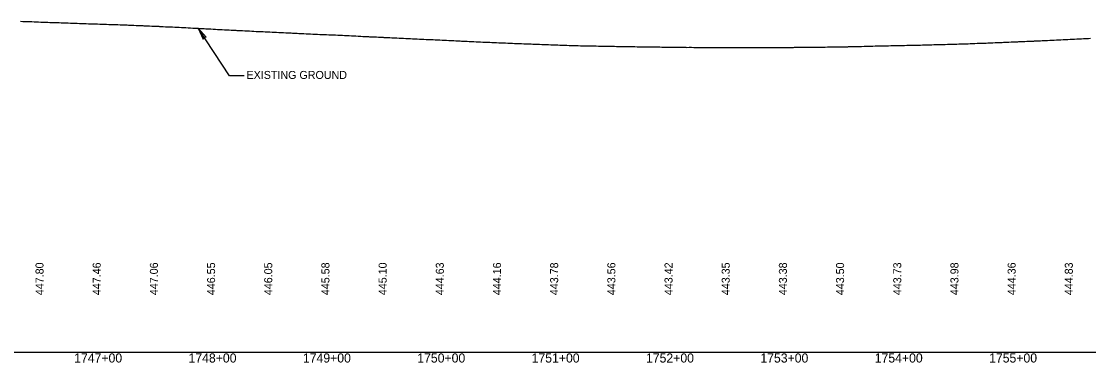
# Model space of a CAD drawing. Extents: x 2017200 to 2047700, y 854850 to 893350.
# Drawn here: x 2029630 to 2030563, y 859091 to 859390 of the extents above; entities that cross this region are included whole.
import ezdxf

# ---------------------------------------------------------------- set-up
doc = ezdxf.new("R2010")
doc.units = 0
for name, color, linetype in [('RD_DDB_Profile_EX', 7, 'Continuous'), ('RD_DDB_Profile_Lbl', 7, 'Continuous'), ('RD_DDB_StaTX', 7, 'Continuous'), ('RD_DDB_StripGrade', 7, 'Continuous'), ('RD_GPK_Profile_Cell', 7, 'Continuous')]:
    doc.layers.add(name, color=color, linetype=linetype)

msp = doc.modelspace()

# ---------------------------------------------------------------- linework, layer by layer
at = {"layer": 'RD_DDB_Profile_EX'}
msp.add_lwpolyline([(2029628.81, 859389.7), (2029630.78, 859389.63), (2029632.79, 859389.56), (2029634.76, 859389.54), (2029635.28, 859389.53), (2029636.74, 859389.5), (2029638.72, 859389.41), (2029640.76, 859389.34), (2029642.05, 859389.3), (2029642.76, 859389.28), (2029644.74, 859389.19), (2029646.72, 859389.09), (2029648.82, 859389.03), (2029650.67, 859389), (2029652.68, 859388.89), (2029654.65, 859388.81), (2029655.59, 859388.79), (2029656.63, 859388.75), (2029658.61, 859388.7), (2029660.58, 859388.6), (2029662.58, 859388.54), (2029664.56, 859388.48), (2029666.54, 859388.41), (2029668.52, 859388.31), (2029669.13, 859388.3), (2029670.5, 859388.26), (2029672.51, 859388.2), (2029674.48, 859388.13), (2029675.9, 859388.07), (2029676.46, 859388.05), (2029678.43, 859387.98), (2029680.4, 859387.9), (2029682.67, 859387.8), (2029684.38, 859387.76), (2029686.36, 859387.71), (2029688.33, 859387.61), (2029689.44, 859387.58), (2029690.31, 859387.55), (2029692.31, 859387.51), (2029694.28, 859387.44), (2029696.26, 859387.37), (2029698.24, 859387.32), (2029700.22, 859387.28), (2029702.22, 859387.21), (2029702.98, 859387.18), (2029704.19, 859387.13), (2029706.17, 859387.06), (2029708.14, 859387.04), (2029709.75, 859386.96), (2029710.11, 859386.95), (2029712.11, 859386.87), (2029714.08, 859386.81), (2029716.06, 859386.75), (2029716.52, 859386.73), (2029718.03, 859386.66), (2029720, 859386.57), (2029722, 859386.51), (2029723.29, 859386.44), (2029723.98, 859386.41), (2029725.96, 859386.3), (2029727.93, 859386.24), (2029730.06, 859386.16), (2029731.91, 859386.06), (2029733.89, 859385.99), (2029735.86, 859385.94), (2029736.83, 859385.89), (2029737.84, 859385.83), (2029739.81, 859385.72), (2029741.81, 859385.66), (2029743.79, 859385.58), (2029745.77, 859385.48), (2029747.75, 859385.39), (2029749.73, 859385.34), (2029750.37, 859385.3), (2029751.73, 859385.22), (2029753.71, 859385.12), (2029755.69, 859384.99), (2029757.14, 859384.97), (2029757.67, 859384.96), (2029759.65, 859384.86), (2029761.66, 859384.74), (2029763.91, 859384.65), (2029765.61, 859384.55), (2029767.59, 859384.45), (2029769.56, 859384.34), (2029770.68, 859384.3), (2029771.56, 859384.26), (2029773.54, 859384.15), (2029775.52, 859384.05), (2029777.49, 859383.95), (2029779.47, 859383.85), (2029781.47, 859383.74), (2029783.45, 859383.64), (2029784.22, 859383.6), (2029785.42, 859383.54), (2029787.4, 859383.43), (2029789.37, 859383.32), (2029790.99, 859383.24), (2029791.37, 859383.22), (2029793.35, 859383.1), (2029795.32, 859382.99), (2029797.3, 859382.87), (2029797.76, 859382.84), (2029799.27, 859382.77), (2029801.27, 859382.68), (2029803.26, 859382.58), (2029804.53, 859382.51), (2029805.24, 859382.47), (2029807.22, 859382.36), (2029809.2, 859382.26), (2029811.3, 859382.16), (2029813.18, 859382.05), (2029815.16, 859381.97), (2029817.13, 859381.87), (2029818.07, 859381.81), (2029819.11, 859381.75), (2029821.11, 859381.65), (2029823.09, 859381.56), (2029825.06, 859381.46), (2029827.04, 859381.33), (2029829.01, 859381.25), (2029831.01, 859381.14), (2029831.61, 859381.11), (2029832.99, 859381.03), (2029834.96, 859380.93), (2029836.94, 859380.87), (2029838.38, 859380.79), (2029838.91, 859380.75), (2029840.92, 859380.65), (2029842.89, 859380.56), (2029845.15, 859380.48), (2029845.53, 859380.46), (2029846.84, 859380.39), (2029848.82, 859380.31), (2029850.82, 859380.22), (2029851.92, 859380.17), (2029852.8, 859380.12), (2029854.78, 859380.03), (2029856.75, 859379.94), (2029858.73, 859379.84), (2029860.73, 859379.76), (2029862.71, 859379.69), (2029864.69, 859379.57), (2029865.46, 859379.53), (2029866.67, 859379.46), (2029868.64, 859379.39), (2029870.65, 859379.26), (2029872.23, 859379.18), (2029872.62, 859379.15), (2029874.6, 859379.07), (2029876.58, 859378.97), (2029878.55, 859378.84), (2029879, 859378.83), (2029880.56, 859378.77), (2029882.53, 859378.7), (2029884.51, 859378.57), (2029885.77, 859378.51), (2029886.49, 859378.48), (2029888.46, 859378.4), (2029890.47, 859378.3), (2029892.54, 859378.21), (2029894.42, 859378.14), (2029896.4, 859378.06), (2029898.37, 859377.97), (2029899.31, 859377.93), (2029900.38, 859377.88), (2029902.36, 859377.8), (2029904.33, 859377.75), (2029906.31, 859377.62), (2029908.29, 859377.54), (2029910.29, 859377.46), (2029912.27, 859377.39), (2029912.85, 859377.35), (2029914.24, 859377.27), (2029916.22, 859377.18), (2029918.2, 859377.11), (2029919.62, 859377.01), (2029920.2, 859376.98), (2029922.18, 859376.89), (2029924.16, 859376.8), (2029926.39, 859376.64), (2029928.11, 859376.55), (2029930.11, 859376.5), (2029932.09, 859376.41), (2029933.16, 859376.33), (2029934.07, 859376.27), (2029936.04, 859376.17), (2029938.02, 859376.13), (2029940.02, 859376.01), (2029942, 859375.89), (2029943.98, 859375.82), (2029945.95, 859375.72), (2029946.7, 859375.68), (2029947.93, 859375.62), (2029949.93, 859375.51), (2029951.91, 859375.43), (2029953.47, 859375.35), (2029953.89, 859375.33), (2029955.86, 859375.23), (2029957.84, 859375.12), (2029959.84, 859375.05), (2029960.24, 859375.03), (2029961.82, 859374.96), (2029963.8, 859374.87), (2029965.77, 859374.75), (2029967.01, 859374.73), (2029967.75, 859374.71), (2029969.75, 859374.6), (2029971.73, 859374.49), (2029973.78, 859374.38), (2029975.68, 859374.34), (2029977.66, 859374.22), (2029979.66, 859374.12), (2029980.55, 859374.08), (2029981.64, 859374.03), (2029983.62, 859373.93), (2029985.59, 859373.84), (2029987.57, 859373.76), (2029989.57, 859373.68), (2029991.55, 859373.56), (2029993.53, 859373.47), (2029994.09, 859373.45), (2029995.5, 859373.41), (2029997.48, 859373.3), (2029999.48, 859373.18), (2030000.86, 859373.12), (2030001.46, 859373.09), (2030003.44, 859372.99), (2030005.41, 859372.91), (2030007.63, 859372.77), (2030009.39, 859372.66), (2030011.37, 859372.59), (2030013.35, 859372.48), (2030014.4, 859372.41), (2030015.32, 859372.36), (2030017.3, 859372.28), (2030019.3, 859372.19), (2030021.28, 859372.09), (2030023.26, 859372), (2030025.23, 859371.94), (2030027.21, 859371.84), (2030027.94, 859371.8), (2030029.22, 859371.73), (2030031.19, 859371.65), (2030033.17, 859371.57), (2030034.71, 859371.48), (2030035.15, 859371.45), (2030037.13, 859371.37), (2030039.13, 859371.32), (2030041.11, 859371.21), (2030041.48, 859371.19), (2030043.08, 859371.1), (2030045.06, 859371.05), (2030047.04, 859370.98), (2030048.25, 859370.9), (2030049.04, 859370.85), (2030051.02, 859370.78), (2030052.99, 859370.75), (2030055.02, 859370.64), (2030056.95, 859370.53), (2030058.95, 859370.5), (2030060.93, 859370.43), (2030061.79, 859370.39), (2030062.9, 859370.33), (2030064.88, 859370.25), (2030066.86, 859370.17), (2030068.86, 859370.11), (2030070.84, 859370.01), (2030072.81, 859369.94), (2030074.79, 859369.88), (2030075.33, 859369.86), (2030076.77, 859369.8), (2030078.77, 859369.71), (2030080.75, 859369.64), (2030082.1, 859369.6), (2030082.72, 859369.59), (2030084.7, 859369.48), (2030086.68, 859369.42), (2030088.87, 859369.39), (2030090.66, 859369.28), (2030092.63, 859369.19), (2030094.61, 859369.11), (2030095.64, 859369.1), (2030096.59, 859369.08), (2030098.59, 859368.98), (2030100.57, 859368.9), (2030102.55, 859368.87), (2030104.52, 859368.79), (2030106.5, 859368.71), (2030108.5, 859368.67), (2030109.18, 859368.66), (2030110.48, 859368.63), (2030112.46, 859368.52), (2030114.43, 859368.5), (2030115.95, 859368.49), (2030116.41, 859368.48), (2030118.42, 859368.39), (2030120.39, 859368.34), (2030122.37, 859368.32), (2030122.72, 859368.31), (2030124.35, 859368.3), (2030126.32, 859368.22), (2030128.33, 859368.19), (2030129.49, 859368.18), (2030130.3, 859368.17), (2030132.28, 859368.13), (2030134.26, 859368.06), (2030136.26, 859368.04), (2030138.24, 859368.03), (2030140.22, 859367.96), (2030142.19, 859367.92), (2030143.03, 859367.92), (2030144.17, 859367.9), (2030146.15, 859367.88), (2030148.15, 859367.81), (2030150.13, 859367.78), (2030152.1, 859367.77), (2030154.08, 859367.69), (2030156.06, 859367.67), (2030156.57, 859367.67), (2030158.06, 859367.66), (2030160.03, 859367.61), (2030162.01, 859367.57), (2030163.34, 859367.55), (2030163.99, 859367.54), (2030165.97, 859367.54), (2030167.97, 859367.49), (2030170.11, 859367.46), (2030171.92, 859367.47), (2030173.9, 859367.43), (2030175.88, 859367.38), (2030176.88, 859367.38), (2030177.88, 859367.37), (2030179.85, 859367.38), (2030181.83, 859367.3), (2030183.81, 859367.28), (2030185.78, 859367.3), (2030187.79, 859367.24), (2030189.76, 859367.21), (2030190.42, 859367.2), (2030191.74, 859367.19), (2030193.72, 859367.2), (2030195.69, 859367.15), (2030197.19, 859367.11), (2030197.7, 859367.1), (2030199.67, 859367.11), (2030201.65, 859367.06), (2030203.63, 859367.03), (2030203.96, 859367.03), (2030205.61, 859367.03), (2030207.61, 859367.01), (2030209.59, 859366.98), (2030210.73, 859366.95), (2030211.56, 859366.93), (2030213.54, 859366.97), (2030215.52, 859366.94), (2030217.52, 859366.92), (2030219.5, 859366.92), (2030221.47, 859366.9), (2030223.45, 859366.87), (2030224.27, 859366.85), (2030225.43, 859366.83), (2030227.43, 859366.84), (2030229.41, 859366.84), (2030231.38, 859366.82), (2030233.36, 859366.82), (2030235.34, 859366.8), (2030237.34, 859366.8), (2030237.81, 859366.8), (2030239.32, 859366.8), (2030241.3, 859366.78), (2030243.27, 859366.77), (2030244.58, 859366.8), (2030245.25, 859366.82), (2030247.25, 859366.76), (2030249.23, 859366.75), (2030251.35, 859366.79), (2030253.18, 859366.77), (2030255.16, 859366.72), (2030257.16, 859366.74), (2030258.12, 859366.74), (2030259.14, 859366.75), (2030261.11, 859366.71), (2030263.09, 859366.72), (2030265.07, 859366.75), (2030267.07, 859366.73), (2030269.05, 859366.71), (2030271.02, 859366.73), (2030271.66, 859366.74), (2030273, 859366.75), (2030274.98, 859366.72), (2030276.98, 859366.74), (2030278.43, 859366.76), (2030278.96, 859366.77), (2030280.93, 859366.75), (2030282.91, 859366.75), (2030284.89, 859366.79), (2030285.2, 859366.79), (2030286.89, 859366.79), (2030288.87, 859366.79), (2030290.84, 859366.78), (2030291.97, 859366.83), (2030292.82, 859366.86), (2030294.8, 859366.84), (2030296.8, 859366.85), (2030298.78, 859366.9), (2030300.75, 859366.92), (2030302.73, 859366.9), (2030304.71, 859366.92), (2030305.51, 859366.94), (2030306.71, 859366.97), (2030308.69, 859366.97), (2030310.66, 859366.98), (2030312.28, 859367.02), (2030312.64, 859367.03), (2030314.62, 859367.05), (2030316.62, 859367.05), (2030318.6, 859367.07), (2030319.05, 859367.08), (2030320.57, 859367.12), (2030322.55, 859367.11), (2030324.53, 859367.11), (2030325.82, 859367.14), (2030326.53, 859367.15), (2030328.51, 859367.2), (2030330.48, 859367.21), (2030332.59, 859367.22), (2030334.44, 859367.26), (2030336.44, 859367.27), (2030338.42, 859367.31), (2030339.36, 859367.32), (2030340.39, 859367.34), (2030342.37, 859367.36), (2030344.35, 859367.39), (2030346.35, 859367.43), (2030348.33, 859367.48), (2030350.3, 859367.5), (2030352.28, 859367.51), (2030352.89, 859367.54), (2030354.26, 859367.6), (2030356.26, 859367.62), (2030358.23, 859367.65), (2030359.66, 859367.69), (2030360.21, 859367.7), (2030362.19, 859367.78), (2030364.17, 859367.8), (2030366.43, 859367.84), (2030368.14, 859367.91), (2030370.12, 859367.95), (2030372.1, 859367.98), (2030373.2, 859368), (2030374.07, 859368.02), (2030376.07, 859368.12), (2030378.05, 859368.15), (2030380.03, 859368.18), (2030382.01, 859368.24), (2030383.98, 859368.33), (2030385.99, 859368.34), (2030386.74, 859368.36), (2030387.97, 859368.39), (2030389.94, 859368.47), (2030391.92, 859368.5), (2030393.51, 859368.52), (2030393.9, 859368.52), (2030395.9, 859368.57), (2030397.88, 859368.66), (2030399.85, 859368.64), (2030400.28, 859368.65), (2030401.83, 859368.68), (2030403.81, 859368.74), (2030405.81, 859368.78), (2030407.05, 859368.8), (2030407.79, 859368.81), (2030409.76, 859368.85), (2030411.74, 859368.9), (2030413.82, 859368.92), (2030415.72, 859368.97), (2030417.7, 859369.04), (2030419.68, 859369.09), (2030420.59, 859369.11), (2030421.66, 859369.13), (2030423.63, 859369.17), (2030425.64, 859369.24), (2030427.62, 859369.28), (2030429.59, 859369.32), (2030431.57, 859369.37), (2030433.55, 859369.44), (2030434.13, 859369.45), (2030435.55, 859369.47), (2030437.53, 859369.53), (2030439.51, 859369.6), (2030440.9, 859369.62), (2030441.49, 859369.63), (2030443.47, 859369.69), (2030445.47, 859369.76), (2030447.67, 859369.83), (2030449.43, 859369.87), (2030451.41, 859369.95), (2030453.39, 859370.03), (2030454.44, 859370.06), (2030455.39, 859370.09), (2030457.37, 859370.14), (2030459.34, 859370.22), (2030461.32, 859370.32), (2030463.3, 859370.38), (2030465.3, 859370.44), (2030467.28, 859370.52), (2030467.98, 859370.55), (2030469.26, 859370.6), (2030471.24, 859370.64), (2030473.21, 859370.71), (2030474.75, 859370.79), (2030475.22, 859370.82), (2030477.2, 859370.88), (2030479.17, 859370.94), (2030481.15, 859371.03), (2030481.52, 859371.05), (2030483.13, 859371.13), (2030485.13, 859371.2), (2030487.11, 859371.27), (2030488.29, 859371.33), (2030489.09, 859371.37), (2030491.06, 859371.43), (2030493.04, 859371.51), (2030495.06, 859371.62), (2030497.02, 859371.72), (2030499, 859371.78), (2030500.97, 859371.86), (2030501.83, 859371.91), (2030502.95, 859371.98), (2030504.95, 859372.04), (2030506.93, 859372.11), (2030508.91, 859372.2), (2030510.88, 859372.31), (2030512.86, 859372.36), (2030514.86, 859372.46), (2030515.37, 859372.48), (2030516.84, 859372.54), (2030518.82, 859372.63), (2030520.79, 859372.73), (2030522.14, 859372.8), (2030522.77, 859372.83), (2030524.77, 859372.9), (2030526.75, 859373), (2030528.91, 859373.11), (2030530.7, 859373.19), (2030532.68, 859373.25), (2030534.68, 859373.39), (2030535.68, 859373.44), (2030536.65, 859373.49), (2030538.63, 859373.57), (2030540.6, 859373.65), (2030542.58, 859373.79), (2030544.58, 859373.88), (2030546.55, 859373.95), (2030548.53, 859374.07), (2030549.22, 859374.12), (2030550.5, 859374.2), (2030552.48, 859374.26), (2030554.48, 859374.35), (2030555.99, 859374.43), (2030556.46, 859374.46), (2030558.43, 859374.57), (2030560.41, 859374.68), (2030562.39, 859374.78), (2030562.76, 859374.8), (2030564.39, 859374.89)], dxfattribs=at)
at = {"layer": 'RD_DDB_Profile_Lbl'}
for p, q in [((2029811.68, 859341.89), (2029784.22, 859383.6)), ((2029824.54, 859341.89), (2029811.68, 859341.89))]:
    msp.add_line(p, q, dxfattribs=at)
msp.add_lwpolyline([(2029784.22, 859383.6), (2029788.68, 859374.1), (2029789.05, 859376.26), (2029791.18, 859375.75)], close=True, dxfattribs=at)
at = {"layer": 'RD_GPK_Profile_Cell'}
msp.add_line((2020500, 859100), (2047700, 859100), dxfattribs=at)

# ---------------------------------------------------------------- texts
at = {"layer": 'RD_DDB_Profile_Lbl'}
msp.add_text('EXISTING GROUND', height=7, dxfattribs=at).set_placement((2029826.48, 859339.27))
at = {"layer": 'RD_DDB_StaTX'}
for s, p in [('1747+00', (2029675.8, 859091)), ('1748+00', (2029775.8, 859091)), ('1749+00', (2029875.8, 859091)), ('1750+00', (2029975.8, 859091)), ('1751+00', (2030075.8, 859091)), ('1752+00', (2030175.8, 859091)), ('1753+00', (2030275.8, 859091)), ('1754+00', (2030375.8, 859091)), ('1755+00', (2030475.8, 859091))]:
    msp.add_text(s, height=8, dxfattribs=at).set_placement(p)
at = {"layer": 'RD_DDB_StripGrade'}
for s, p in [('447.80', (2029649, 859150)), ('447.46', (2029699, 859150)), ('447.06', (2029749, 859150)), ('446.55', (2029799, 859150)), ('446.05', (2029849, 859150)), ('445.58', (2029899, 859150)), ('445.10', (2029949, 859150)), ('444.63', (2029999, 859150)), ('444.16', (2030049, 859150)), ('443.78', (2030099, 859150)), ('443.56', (2030149, 859150)), ('443.42', (2030199, 859150)), ('443.35', (2030249, 859150)), ('443.38', (2030299, 859150)), ('443.50', (2030349, 859150)), ('443.73', (2030399, 859150)), ('443.98', (2030449, 859150)), ('444.36', (2030499, 859150)), ('444.83', (2030549, 859150))]:
    msp.add_text(s, height=7, rotation=90, dxfattribs=at).set_placement(p)

doc.saveas('drawing.dxf')
